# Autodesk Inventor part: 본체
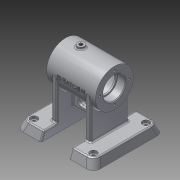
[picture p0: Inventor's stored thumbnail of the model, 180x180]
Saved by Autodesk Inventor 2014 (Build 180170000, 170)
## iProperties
Created: 2016-07
Part Number: 본체
Material: 알루미늄 6061
Document SubType Name: Modeling
Designer: basic
Density: 2.71 g/cm^3
Appearance: 알루미늄 - 평지
Mass: 473.747 g
Surface Area: 532.523 cm^2
Volume: 174.814 cm^3
Author: basic
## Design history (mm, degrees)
sketch "스케치12"
  geometry: L1 (35, 0)-(-35, 0); L2 (35, 0)-(35, 27); L3 (35, 27)-(-35, 27); L4 (-35, 27)-(-35, 0); L5 (35, 16)-(23, 16); L6 (23, 16)-(23, 14); L7 (23, 14)-(21, 14); L8 (21, 14)-(21, 22); L9 (21, 22)-(-21, 22); L10 (-21, 22)-(-21, 14); L11 (-21, 14)-(-23, 14); L12 (-23, 14)-(-23, 16); L13 (-23, 16)-(-35, 16); 2 further points
  constraints: 26 end point, 7 parallel, 5 perpendicular, 3 equal length, 2 point on line, 1 coincident, 1 horizontal, 1 midpoint
  dimensions: "d36" = 70 distance of L1.start L1.end; "d37" = 54 diameter of L3 L1; "d38" = 44 diameter of L9 L1; "d39" = 32 diameter of L5 L1; "d40" = 28 diameter of L7 L1; "d41" = 12 distance of L5.start L5.end; "d42" = 42 distance of L8.end L9.end; "d43" = 32 diameter of L13 L1
revolve "회전1" sketch "스케치12" stored, may be unused: angle "d44" = 90 deg
node "작업 평면3"
sketch "스케치13"
  geometry: L1 (-55, 50)-(55, 50); L2 (55, 50)-(55, -50); L3 (55, -50)-(-55, -50); L4 (-55, -50)-(-55, 50); L5 (-55, 50)-(55, -50); L6 (55, 50)-(-55, -50); 1 further point
  constraints: 12 end point, 2 midpoint, 2 parallel, 1 horizontal, 1 perpendicular
  dimensions: "d46" = 100 distance of L3.end L1.start; "d47" = 110 distance of L2.end L3.end
extrude "돌출7" join sketch "스케치13" distance "d48" = 12; taper "d49" = -20 deg
sketch "스케치14"
  geometry: L1 (55, 50)-(-55, 50) reference; L2 (-20, -50)-(20, -50); L3 (20, -50)-(20, 50); L4 (20, 50)-(-20, 50); L5 (-20, 50)-(-20, -50); L6 (-20, -50)-(20, 50); L7 (20, -50)-(-20, 50); 3 further points
  constraints: 12 end point, 2 midpoint, 2 parallel, 1 horizontal, 1 perpendicular, 1 point on line
  dimensions: "d52" = 40 distance of L3.end L4.end
extrude "돌출8" cut sketch "스케치14" stored distance "d53" = 10; taper "d54" = 0 deg
sketch "스케치15"
  geometry: L1 (20, 45.632)-(20, -45.632) reference; L2 (-20, 50)-(-20, -50) reference; L3 (55, -50)-(20, -50) reference; L4 (-55, -50)-(-55, 50) reference; L5 (-55, 50)-(-20, 50) reference; L6 (-20, -27)-(-28, -27); L7 (-28, -27)-(-28, 27); L8 (-28, 27)-(-20, 27); L9 (-20, 27)-(-20, -27); L10 (20, -27)-(28, -27); L11 (28, -27)-(28, 27); L12 (28, 27)-(20, 27); L13 (20, 27)-(20, -27); L14 (20, -50)-(20, 50) reference; L15 (20, 50)-(55, 50) reference; L16 (55, 50)-(55, -50) reference; L17 (-20, -50)-(-55, -50) reference; 5 further points
  constraints: 16 end point, 4 parallel, 2 horizontal, 2 horizontal alignment, 2 midpoint, 2 perpendicular, 2 point on line
  dimensions: "d55" = 54 distance of L8.end L6.start; "d56" = 8 distance of L6.start L6.end; "d57" = 54 distance of L12.end L10.start; "d58" = 8 distance of L10.start L10.end
extrude "돌출9" join sketch "스케치15" stored distance "d59" = 10; taper "d60" = 0 deg
sketch "스케치16"
  geometry: L1 (21, 22)-(-21, 22) reference; L2 (-21, 22)-(-21, 14) reference; L3 (-21, 14)-(-23, 14) reference; L4 (-23, 14)-(-23, 16) reference; L5 (-23, 16)-(-35, 16) reference; L6 (-35, 16)-(-35, 27) reference; L7 (-35, 27)-(35, 27) reference; L8 (35, 27)-(35, 16) reference; L9 (35, 16)-(23, 16) reference; L10 (23, 16)-(23, 14) reference; L11 (23, 14)-(21, 14) reference; L12 (21, 14)-(21, 22) reference; L13 (-21, -22)-(21, -22) reference; L14 (21, -22)-(21, -14) reference; L15 (21, -14)-(23, -14) reference; L16 (23, -14)-(23, -16) reference; L17 (23, -16)-(35, -16) reference; L18 (35, -16)-(35, -27) reference; L19 (35, -27)-(28, -27) reference; L20 (28, -27)-(28, -58) reference; L21 (28, -58)-(50.632, -58) reference; L22 (50.632, -58)-(55, -70) reference; L23 (55, -70)-(20, -70) reference; L24 (20, -70)-(20, -27) reference; L25 (20, -27)-(-20, -27) reference; L26 (-20, -27)-(-20, -70) reference; L27 (-20, -70)-(-55, -70) reference; L28 (-55, -70)-(-50.632, -58) reference; L29 (-50.632, -58)-(-28, -58) reference; L30 (-28, -58)-(-28, -27) reference; L31 (-28, -27)-(-35, -27) reference; L32 (-35, -27)-(-35, -16) reference; L33 (-35, -16)-(-23, -16) reference; L34 (-23, -16)-(-23, -14) reference; L35 (-23, -14)-(-21, -14) reference; L36 (-21, -14)-(-21, -22) reference; L37 (20, -48)-(-20, -48); 1 further point
  constraints: 2 end point, 2 point on line, 1 perpendicular
  dimensions: "d62" = 21 distance between parallel lines of L37 L25
feature "리브1" sketch "스케치16" dims "d63" = 1, "d64" = 8, "d65" = 0, "d66" = 0, "d67" = 1, "d68" = 1
sketch "스케치17"
  geometry: L1 (0, 0)-(40, 0) reference; L2 (12, -11.298)-(28, -11.298); L3 (12, -14.798)-(28, -14.798); L4 (28, -7.798)-(12, -7.798); L5 (40, -31.298)-(40, -43.298) reference; L6 (75, -43.298)-(40, -43.298) reference; L7 (-15, 53.702)-(-15, -0.298) reference; L8 (75, -43.298)-(70.632, -31.298) reference; L9 (0, -43.298)-(0, -31.298) reference; L10 (-35, -43.298)-(-30.632, -31.298) reference; L11 (0, -43.298)-(-35, -43.298) reference; L12 (70.632, -31.298)-(40, -31.298) reference; L13 (0, -31.298)-(-30.632, -31.298) reference; A1 r 3.5 centre (12, -11.298) between (12, -7.798) and (12, -14.798); A2 r 3.5 centre (28, -11.298) between (28, -14.798) and (28, -7.798); 2 further points
  constraints: 8 end point, 4 point on circle, 4 tangent, 2 centre point, 2 parallel, 1 midpoint
  dimensions: "d69" = 32 distance from line of L6 point (20, -11.298); "d70" = 35 distance from line of L7 point (20, -11.298); "d71" = 23 dimension on A2 A1; "d72" = 3.5 radius of A2
extrude "돌출10" cut sketch "스케치17" stored distance "d73" = 10; taper "d74" = 0 deg
fillet "모깎기6" dims "d75" = 2
sketch "스케치18"
  geometry: L1 (0, 0)-(-21, 0); C1 r 16 at (0, 0) reference; 1 further point
  constraints: 2 end point, 1 coincident, 1 horizontal
  dimensions: "d76" = 21 distance of L1.start L1.end
hole "구멍1" sketch "스케치18" at (-21, 0) diameter "d77" = 3.242; stored, may be unused: countersink angle "d81" = 90 deg, drill point angle "d83" = 118 deg; dims "d78" = 8, "d79" = 4, "d80" = 2, "d82" = 10
node "작업 평면5"
sketch "스케치20"
  geometry: L1 (35, -27)-(35, 27) reference; L2 (35, 0)-(13, 0); C1 r 5 at (13, 0); 1 further point
  constraints: 2 end point, 1 centre point, 1 coincident, 1 midpoint, 1 perpendicular
  dimensions: "d91" = 22 distance of L2.start L2.end; "d92" = 10 diameter of C1
extrude "돌출11" join sketch "스케치20" stored distance "d93" = 10; taper "d94" = 0 deg
sketch "스케치21"
  geometry: C1 r 5 at (0, 0) reference; 2 further points
  constraints: 1 coincident
hole "구멍2" sketch "스케치21" at (0, 0) diameter "d95" = 5.188; stored, may be unused: countersink angle "d99" = 90 deg, drill point angle "d101" = 118 deg; dims "d96" = 8, "d97" = 4, "d98" = 2, "d100" = 10
fillet "모깎기7" dims "d102" = 2
chamfer "모따기1" distance "d103" = 1; stored, may be unused: second distance "d104" = 2, angle "d105" = 45 deg
fillet "모깎기8" dims "d106" = 0.3
fillet "모깎기9" dims "d107" = 3
fillet "모깎기10" dims "d108" = 2
fillet "모깎기11" dims "d109" = 2
fillet "모깎기12" dims "d110" = 2
fillet "모깎기13" dims "d111" = 2
fillet "모깎기14" dims "d112" = 2
node "작업 평면7"
sketch "스케치23"
  geometry: L1 (35, 27)-(-35, 27) reference; L2 (-35, 27)-(-35, -27) reference; 2 further points
  constraints: 1 other
  dimensions: "d115" = 35 distance from line of L2 point (0, 0); "d116" = 27 distance from line of point (0, 0) L1
feature "엠보싱1" sketch "스케치23" dims "d36" = 70, "d37" = 54, "d38" = 44, "d39" = 32, "d40" = 28, "d41" = 12, "d42" = 42, "d43" = 32, "d46" = 100, "d47" = 110, "d117" = 0.5, "d118" = 0
fillet "모깎기16" dims "d120" = 2
fillet "모깎기17" dims "d121" = 2
fillet "모깎기18" dims "d122" = 10
sketch "스케치26"
  geometry: L1 (-41.714, 44.232)-(-22, 44.232) reference; L2 (0, 0)-(42.5, 0); L3 (42.5, 0)-(42.5, 37.5); 1 further point
  constraints: 4 end point, 1 coincident, 1 parallel, 1 perpendicular
  dimensions: "d123" = 42.5 distance of L2.start L2.end; "d124" = 37.5 distance of L2.end L3.end
hole "구멍3" sketch "스케치26" at (42.5, 37.5) diameter "d125" = 6; stored, may be unused: countersink angle "d129" = 90 deg, drill point angle "d131" = 118 deg; dims "d126" = 6, "d127" = 10, "d128" = 4, "d130" = 10
sketch "스케치27"
  geometry: L1 (4, -43.5)-(4, -46) reference; L2 (2, -48)-(-2, -48) reference; L3 (-4, -46)-(-4, -43.5) reference; L4 (-2, -41.5)-(2, -41.5) reference; L5 (2, -34.5)-(-2, -34.5) reference; L6 (-4, -32.5)-(-4, -28.373) reference; L7 (-26.928, 1.971)-(-27.429, 1.971) reference; L8 (-27.396, 2.385)-(-26.894, 2.385) reference; L9 (4, -28.373)-(4, -32.5) reference; L10 (0, 0)-(15.898, -25.441); L11 (15.898, -25.441)-(10.809, -28.621); L12 (10.809, -28.621)-(6.57, -21.837); L13 (11.658, -18.657)-(6.57, -21.837); C1 r 22 at (0, 0) reference; A1 r 2 centre (2, -43.5) between (4, -43.5) and (2, -41.5) reference; A2 r 2 centre (2, -46) between (2, -48) and (4, -46) reference; A3 r 2 centre (-2, -46) between (-4, -46) and (-2, -48) reference; A4 r 2 centre (-2, -43.5) between (-2, -41.5) and (-4, -43.5) reference; A5 r 2 centre (2, -32.5) between (2, -34.5) and (4, -32.5) reference; A6 r 2 centre (-2, -32.5) between (-4, -32.5) and (-2, -34.5) reference; A7 r 2 centre (-6, -28.373) between (-4, -28.373) and (-5.586, -26.416) reference; A8 r 27 centre (0, 0) between (-26.928, 1.971) and (-5.586, -26.416) reference; A9 r 27.5 centre (0, 0) between (-27.396, 2.385) and (-27.429, 1.971) reference; A10 r 27 centre (0, 0) between (5.586, -26.416) and (-26.894, 2.385) reference; A11 r 2 centre (6, -28.373) between (5.586, -26.416) and (4, -28.373) reference; 1 further point
  constraints: 8 end point, 3 perpendicular, 1 point on line, 1 tangent
  dimensions: "d132" = 32 deg angle of L10 L6; "d133" = 30 distance of L10.start L10.end; "d134" = 6 distance of L10.end L11.end
revolve "회전2" sketch "스케치27" stored, may be unused: angle "d135" = 90 deg
sketch "스케치28"
  geometry: C1 r 6 at (0, 0) reference; 1 further point
  constraints: 1 coincident
hole "구멍4" sketch "스케치28" at (0, 0) diameter "d136" = 5.188; stored, may be unused: countersink angle "d140" = 90 deg, drill point angle "d142" = 118 deg; dims "d137" = 6, "d138" = 10, "d139" = 4, "d141" = 10
fillet "모깎기19" dims "d143" = 2
node "솔리드4"
pattern_circular "원형 패턴1" dims angle "d85" = 360 deg
mirror "대칭1"
mirror "대칭2"
mirror "대칭3"
node "투영된 루프4"
node "투영된 루프5"
node "절단 모서리 투영1"
node "절단 모서리 투영2"
other parameters: "d61" = 21, "d114" = -27
